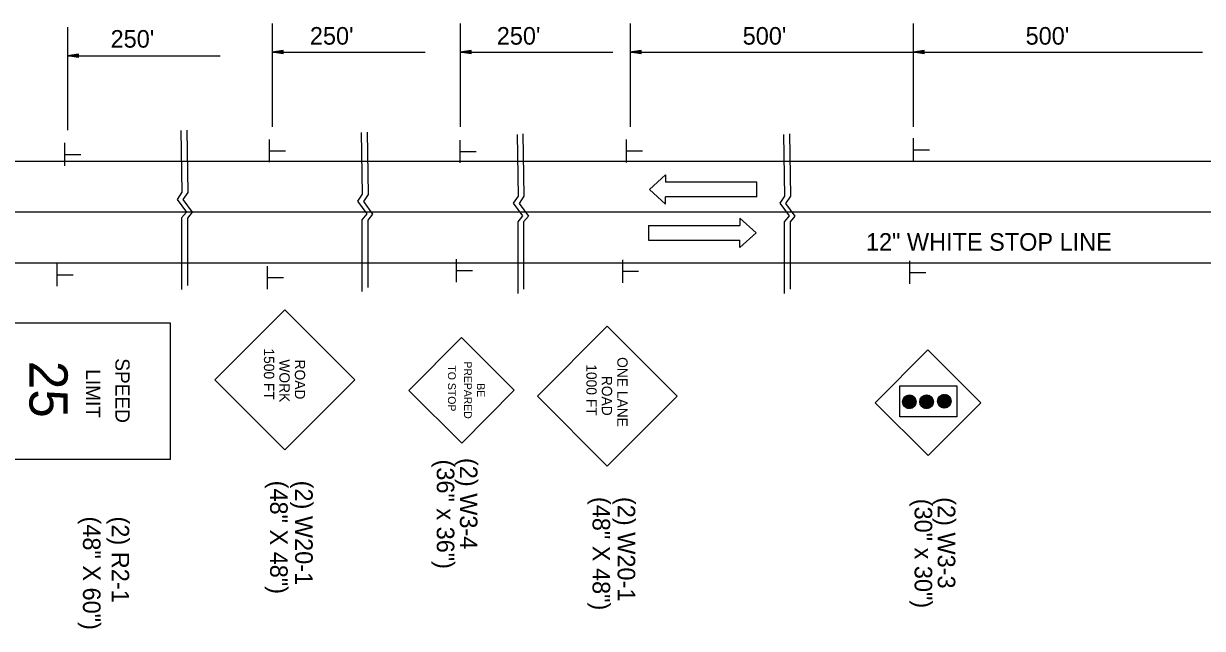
# Model space of a CAD drawing. Extents: x 1678017 to 1687792, y 404433 to 413488.
# Drawn here: x 1683876.8 to 1684279.6, y 411188.4 to 411394.9 of the extents above; entities that cross this region are included whole.
import ezdxf

# ---------------------------------------------------------------- set-up
doc = ezdxf.new("R2010")
doc.units = 0
doc.layers.add('Default', color=7, linetype='Continuous')
doc.layers.add('S_GRAVEL_ROAD', color=7, linetype='Continuous')

msp = doc.modelspace()

# ---------------------------------------------------------------- linework, layer by layer
at = {"layer": 'Default'}
for p, q in [((1683961.8, 411394.85), (1683961.8, 411359.64)), ((1684025.96, 411394.85), (1684025.96, 411359.64)), ((1684084.06, 411394.85), (1684084.06, 411359.64)), ((1684180.71, 411394.85), (1684180.71, 411359.64)), ((1683891.83, 411393.65), (1683891.83, 411358.44)), ((1683895.58, 411384.42), (1683891.83, 411383.86)), ((1683891.83, 411383.86), (1683944.02, 411383.86)), ((1683895.58, 411383.3), (1683891.83, 411383.86)), ((1683895.58, 411384.33), (1683892.46, 411383.86)), ((1683895.58, 411383.39), (1683892.46, 411383.86)), ((1683895.58, 411384.24), (1683893.1, 411383.86)), ((1683895.58, 411383.49), (1683893.1, 411383.86)), ((1683895.58, 411384.14), (1683893.73, 411383.86)), ((1683895.58, 411383.58), (1683893.73, 411383.86)), ((1683895.58, 411384.05), (1683894.36, 411383.86)), ((1683895.58, 411383.68), (1683894.36, 411383.86)), ((1683895.58, 411383.95), (1683894.99, 411383.86)), ((1683895.58, 411383.77), (1683894.99, 411383.86)), ((1683895.58, 411383.3), (1683895.58, 411384.42)), ((1683965.55, 411385.62), (1683961.8, 411385.06)), ((1683961.8, 411385.06), (1684013.99, 411385.06)), ((1683965.55, 411384.5), (1683961.8, 411385.06)), ((1683965.55, 411385.53), (1683962.42, 411385.06)), ((1683965.55, 411384.59), (1683962.42, 411385.06)), ((1683965.55, 411385.43), (1683963.07, 411385.06)), ((1683965.55, 411384.69), (1683963.07, 411385.06)), ((1683965.55, 411385.34), (1683963.69, 411385.06)), ((1683965.55, 411384.78), (1683963.69, 411385.06)), ((1683965.55, 411385.25), (1683964.33, 411385.06)), ((1683965.55, 411384.88), (1683964.33, 411385.06)), ((1683965.55, 411385.15), (1683964.96, 411385.06)), ((1683965.55, 411384.97), (1683964.96, 411385.06)), ((1683965.55, 411384.5), (1683965.55, 411385.62)), ((1684029.71, 411385.62), (1684025.96, 411385.06)), ((1684025.96, 411385.06), (1684078.15, 411385.06)), ((1684029.71, 411384.5), (1684025.96, 411385.06)), ((1684029.71, 411385.53), (1684026.58, 411385.06)), ((1684029.71, 411384.59), (1684026.58, 411385.06)), ((1684029.71, 411385.43), (1684027.23, 411385.06)), ((1684029.71, 411384.69), (1684027.23, 411385.06)), ((1684029.71, 411385.34), (1684027.85, 411385.06)), ((1684029.71, 411384.78), (1684027.85, 411385.06)), ((1684029.71, 411385.25), (1684028.49, 411385.06)), ((1684029.71, 411384.88), (1684028.49, 411385.06)), ((1684029.71, 411385.15), (1684029.12, 411385.06)), ((1684029.71, 411384.97), (1684029.12, 411385.06)), ((1684029.71, 411384.5), (1684029.71, 411385.62)), ((1684087.81, 411385.62), (1684084.06, 411385.06)), ((1684084.06, 411385.06), (1684181.55, 411385.06)), ((1684087.81, 411384.5), (1684084.06, 411385.06)), ((1684087.81, 411385.53), (1684084.69, 411385.06)), ((1684087.81, 411384.59), (1684084.69, 411385.06)), ((1684087.81, 411385.43), (1684085.33, 411385.06)), ((1684087.81, 411384.69), (1684085.33, 411385.06)), ((1684087.81, 411385.34), (1684085.96, 411385.06)), ((1684087.81, 411384.78), (1684085.96, 411385.06)), ((1684087.81, 411385.25), (1684086.59, 411385.06)), ((1684087.81, 411384.88), (1684086.59, 411385.06)), ((1684087.81, 411385.15), (1684087.22, 411385.06)), ((1684087.81, 411384.97), (1684087.22, 411385.06)), ((1684087.81, 411384.5), (1684087.81, 411385.62)), ((1684184.46, 411385.62), (1684180.71, 411385.06)), ((1684180.71, 411385.06), (1684279.55, 411385.06)), ((1684184.46, 411384.5), (1684180.71, 411385.06)), ((1684184.46, 411385.53), (1684181.34, 411385.06)), ((1684184.46, 411384.59), (1684181.34, 411385.06)), ((1684184.46, 411385.43), (1684181.98, 411385.06)), ((1684184.46, 411384.69), (1684181.98, 411385.06)), ((1684184.46, 411385.34), (1684182.61, 411385.06)), ((1684184.46, 411384.78), (1684182.61, 411385.06)), ((1684184.46, 411385.25), (1684183.24, 411385.06)), ((1684184.46, 411384.88), (1684183.24, 411385.06)), ((1684184.46, 411385.15), (1684183.87, 411385.06)), ((1684184.46, 411384.97), (1684183.87, 411385.06)), ((1684184.46, 411384.5), (1684184.46, 411385.62)), ((1683890.92, 411346.31), (1683890.92, 411354.13)), ((1683960.89, 411347.51), (1683960.89, 411355.33)), ((1684025.96, 411347.27), (1684025.96, 411355.09)), ((1684082.76, 411347.48), (1684082.76, 411355.31)), ((1684180.9, 411347.9), (1684180.9, 411355.73)), ((1683891.04, 411350.2), (1683896.38, 411350.2)), ((1683961, 411351.4), (1683966.34, 411351.4)), ((1684026.07, 411351.16), (1684031.41, 411351.16)), ((1684082.88, 411351.37), (1684088.22, 411351.37)), ((1684181.01, 411351.79), (1684186.36, 411351.79)), ((1683849.88, 411347.94), (1683923.82, 411347.94)), ((1683923.82, 411347.94), (1683985.79, 411347.94)), ((1683985.79, 411347.94), (1684046.64, 411347.94)), ((1684046.64, 411347.94), (1684133.24, 411347.94)), ((1684133.24, 411347.94), (1684293.16, 411347.94)), ((1683849.88, 411330.56), (1683924.27, 411330.56)), ((1683924.27, 411330.56), (1683985.45, 411330.56)), ((1683985.45, 411330.56), (1684046.64, 411330.56)), ((1684046.64, 411330.56), (1684133.24, 411330.56)), ((1684133.24, 411330.56), (1684293.16, 411330.56)), ((1684024.69, 411306.63), (1684024.69, 411314.45)), ((1684081.5, 411306.42), (1684081.5, 411314.24)), ((1684179.64, 411305.99), (1684179.64, 411313.82)), ((1683849.88, 411313.17), (1683924.73, 411313.17)), ((1683888.35, 411305.25), (1683888.35, 411313.08)), ((1683924.73, 411313.17), (1683985.11, 411313.17)), ((1683960.21, 411304.24), (1683960.21, 411312.07)), ((1683985.11, 411313.17), (1684059.46, 411313.17)), ((1684024.81, 411310.52), (1684030.15, 411310.52)), ((1684046.64, 411313.17), (1684142.41, 411313.17)), ((1684081.61, 411310.31), (1684086.95, 411310.31)), ((1684133.24, 411313.17), (1684293.16, 411313.17)), ((1684179.75, 411309.88), (1684185.09, 411309.88)), ((1683888.46, 411309.14), (1683893.8, 411309.14)), ((1683960.33, 411308.14), (1683965.67, 411308.14)), ((1683942.22, 411273.26), (1683966.11, 411297.17)), ((1683990.01, 411273.26), (1683966.11, 411297.17)), ((1684052.37, 411267.71), (1684076.25, 411291.61)), ((1684100.16, 411267.71), (1684076.25, 411291.61)), ((1684008.42, 411269.65), (1684026.43, 411287.72)), ((1684044.49, 411269.71), (1684026.43, 411287.72)), ((1684167.77, 411265.4), (1684185.78, 411283.47)), ((1684203.84, 411265.46), (1684185.78, 411283.47)), ((1683966.11, 411249.36), (1683942.22, 411273.26)), ((1683966.11, 411249.36), (1683990.01, 411273.26)), ((1684026.5, 411251.64), (1684008.42, 411269.65)), ((1684026.5, 411251.64), (1684044.49, 411269.71)), ((1684076.25, 411243.81), (1684052.37, 411267.71)), ((1684076.25, 411243.81), (1684100.16, 411267.71)), ((1684185.84, 411247.39), (1684167.77, 411265.4)), ((1684177.11, 411265.8), (1684179.48, 411263.43)), ((1684177.11, 411265.66), (1684179.34, 411263.43)), ((1684177.12, 411265.94), (1684179.62, 411263.44)), ((1684177.12, 411265.5), (1684179.18, 411263.44)), ((1684177.13, 411266.07), (1684179.75, 411263.45)), ((1684177.15, 411266.19), (1684179.87, 411263.47)), ((1684177.15, 411265.33), (1684179.01, 411263.47)), ((1684177.18, 411266.31), (1684179.99, 411263.5)), ((1684177.21, 411266.42), (1684180.1, 411263.53)), ((1684177.24, 411266.53), (1684180.21, 411263.56)), ((1684177.32, 411266.73), (1684180.41, 411263.64)), ((1684177.37, 411266.83), (1684180.51, 411263.69)), ((1684177.42, 411266.92), (1684180.6, 411263.74)), ((1684177.48, 411267.01), (1684180.69, 411263.8)), ((1684177.53, 411267.1), (1684180.78, 411263.85)), ((1684177.59, 411267.18), (1684180.86, 411263.91)), ((1684177.66, 411267.26), (1684180.94, 411263.98)), ((1684177.72, 411267.34), (1684181.02, 411264.04)), ((1684177.79, 411267.41), (1684181.09, 411264.12)), ((1684177.87, 411267.48), (1684181.16, 411264.19)), ((1684177.94, 411267.54), (1684181.22, 411264.26)), ((1684178.02, 411267.61), (1684181.29, 411264.34)), ((1684178.11, 411267.67), (1684181.35, 411264.43)), ((1684178.19, 411267.73), (1684181.41, 411264.51)), ((1684178.28, 411267.78), (1684181.46, 411264.6)), ((1684178.38, 411267.83), (1684181.51, 411264.7)), ((1684178.47, 411267.88), (1684181.56, 411264.79)), ((1684178.57, 411267.92), (1684181.6, 411264.89)), ((1684178.68, 411267.96), (1684181.64, 411265)), ((1684178.79, 411267.99), (1684181.67, 411265.11)), ((1684178.9, 411268.02), (1684181.7, 411265.22)), ((1684179.02, 411268.05), (1684181.73, 411265.34)), ((1684179.14, 411268.07), (1684181.75, 411265.46)), ((1684179.27, 411268.08), (1684181.76, 411265.59)), ((1684179.41, 411268.09), (1684181.77, 411265.73)), ((1684179.55, 411268.08), (1684181.76, 411265.87)), ((1684179.71, 411268.07), (1684181.75, 411266.03)), ((1684179.88, 411268.04), (1684181.72, 411266.2)), ((1684180.07, 411268), (1684181.68, 411266.39)), ((1684180.28, 411267.93), (1684181.61, 411266.6)), ((1684180.55, 411267.8), (1684181.48, 411266.87)), ((1684183, 411265.86), (1684185.43, 411263.43)), ((1684183, 411265.72), (1684185.29, 411263.43)), ((1684183.01, 411266), (1684185.57, 411263.44)), ((1684183.01, 411265.57), (1684185.14, 411263.44)), ((1684183.02, 411265.41), (1684184.98, 411263.46)), ((1684183.03, 411266.12), (1684185.69, 411263.46)), ((1684183.05, 411266.24), (1684185.81, 411263.48)), ((1684183.08, 411266.36), (1684185.93, 411263.51)), ((1684183.11, 411266.47), (1684186.04, 411263.54)), ((1684183.15, 411266.58), (1684186.15, 411263.58)), ((1684183.19, 411266.68), (1684186.25, 411263.62)), ((1684183.23, 411266.78), (1684186.35, 411263.66)), ((1684183.28, 411266.87), (1684186.44, 411263.71)), ((1684183.33, 411266.96), (1684186.53, 411263.77)), ((1684183.39, 411267.05), (1684186.62, 411263.82)), ((1684183.45, 411267.13), (1684186.7, 411263.88)), ((1684183.51, 411267.22), (1684186.78, 411263.94)), ((1684183.58, 411267.29), (1684186.86, 411264.01)), ((1684183.64, 411267.37), (1684186.94, 411264.08)), ((1684183.72, 411267.44), (1684187.01, 411264.15)), ((1684183.79, 411267.51), (1684187.08, 411264.22)), ((1684183.87, 411267.57), (1684187.14, 411264.3)), ((1684183.95, 411267.64), (1684187.2, 411264.38)), ((1684184.03, 411267.69), (1684187.26, 411264.47)), ((1684184.12, 411267.75), (1684187.32, 411264.55)), ((1684184.21, 411267.8), (1684187.37, 411264.64)), ((1684184.31, 411267.85), (1684187.42, 411264.74)), ((1684184.4, 411267.9), (1684187.46, 411264.84)), ((1684184.51, 411267.94), (1684187.51, 411264.94)), ((1684184.61, 411267.97), (1684187.54, 411265.04)), ((1684184.72, 411268.01), (1684187.58, 411265.15)), ((1684184.84, 411268.03), (1684187.6, 411265.27)), ((1684184.96, 411268.06), (1684187.63, 411265.39)), ((1684185.09, 411268.07), (1684187.64, 411265.52)), ((1684185.22, 411268.08), (1684187.65, 411265.65)), ((1684185.36, 411268.09), (1684187.65, 411265.79)), ((1684185.51, 411268.08), (1684187.65, 411265.94)), ((1684185.67, 411268.06), (1684187.63, 411266.1)), ((1684185.84, 411247.39), (1684203.84, 411265.46)), ((1684185.85, 411268.03), (1684187.6, 411266.28)), ((1684186.05, 411267.97), (1684187.54, 411266.48)), ((1684186.28, 411267.88), (1684187.45, 411266.71)), ((1684186.59, 411267.71), (1684187.28, 411267.03)), ((1684189.06, 411266.08), (1684191.5, 411263.65)), ((1684189.06, 411265.94), (1684191.35, 411263.64)), ((1684189.07, 411266.21), (1684191.63, 411263.65)), ((1684189.07, 411265.79), (1684191.2, 411263.65)), ((1684189.09, 411266.34), (1684191.76, 411263.67)), ((1684189.09, 411265.62), (1684191.04, 411263.67)), ((1684189.11, 411266.46), (1684191.88, 411263.69)), ((1684189.12, 411265.45), (1684190.87, 411263.7)), ((1684189.14, 411266.57), (1684191.99, 411263.72)), ((1684189.17, 411266.68), (1684192.1, 411263.75)), ((1684189.21, 411266.79), (1684192.21, 411263.79)), ((1684189.25, 411266.89), (1684192.31, 411263.83)), ((1684189.3, 411266.99), (1684192.41, 411263.88)), ((1684189.34, 411267.08), (1684192.5, 411263.93)), ((1684189.4, 411267.18), (1684192.59, 411263.98)), ((1684189.45, 411267.26), (1684192.68, 411264.03)), ((1684189.51, 411267.35), (1684192.77, 411264.09)), ((1684189.57, 411267.43), (1684192.85, 411264.16)), ((1684189.64, 411267.51), (1684192.92, 411264.22)), ((1684189.71, 411267.58), (1684193, 411264.29)), ((1684189.78, 411267.65), (1684193.07, 411264.36)), ((1684189.85, 411267.72), (1684193.14, 411264.44)), ((1684189.93, 411267.79), (1684193.2, 411264.51)), ((1684190.01, 411267.85), (1684193.27, 411264.59)), ((1684190.1, 411267.91), (1684193.33, 411264.68)), ((1684190.18, 411267.96), (1684193.38, 411264.77)), ((1684190.27, 411268.02), (1684193.43, 411264.86)), ((1684190.37, 411268.06), (1684193.48, 411264.95)), ((1684190.47, 411268.11), (1684193.53, 411265.05)), ((1684190.57, 411268.15), (1684193.57, 411265.15)), ((1684190.68, 411268.19), (1684193.61, 411265.26)), ((1684190.79, 411268.22), (1684193.64, 411265.37)), ((1684190.9, 411268.25), (1684193.67, 411265.48)), ((1684191.02, 411268.27), (1684193.69, 411265.6)), ((1684191.15, 411268.29), (1684193.71, 411265.73)), ((1684191.28, 411268.3), (1684193.72, 411265.86)), ((1684191.42, 411268.3), (1684193.72, 411266)), ((1684191.57, 411268.29), (1684193.71, 411266.16)), ((1684191.73, 411268.27), (1684193.69, 411266.32)), ((1684191.91, 411268.24), (1684193.66, 411266.49)), ((1684192.11, 411268.19), (1684193.6, 411266.69)), ((1684192.34, 411268.1), (1684193.51, 411266.92)), ((1684192.66, 411267.92), (1684193.34, 411267.24)), ((1684177.19, 411265.15), (1684178.83, 411263.51)), ((1684177.26, 411264.94), (1684178.62, 411263.58)), ((1684177.37, 411264.68), (1684178.36, 411263.69)), ((1684177.68, 411264.23), (1684177.9, 411264)), ((1684183.06, 411265.23), (1684184.8, 411263.49)), ((1684183.11, 411265.04), (1684184.6, 411263.54)), ((1684183.2, 411264.8), (1684184.37, 411263.63)), ((1684183.38, 411264.49), (1684184.05, 411263.81)), ((1684189.18, 411265.25), (1684190.67, 411263.76)), ((1684189.27, 411265.02), (1684190.43, 411263.85)), ((1684189.44, 411264.7), (1684190.12, 411264.02))]:
    msp.add_line(p, q, dxfattribs=at)
for points in [[(1683930.61, 411358.31), (1683930.93, 411337.27), (1683929.3, 411334.86), (1683932.47, 411330.53), (1683930.8, 411328.53), (1683930.8, 411304.07)], [(1683932.6, 411358.5), (1683932.92, 411337.19), (1683931.3, 411334.77), (1683934.46, 411330.44), (1683932.8, 411328.44), (1683932.79, 411305.48)], [(1683992.21, 411357.65), (1683992.53, 411336.62), (1683990.91, 411334.2), (1683994.07, 411329.87), (1683992.41, 411327.87), (1683992.4, 411303.42)], [(1683994.21, 411357.84), (1683994.53, 411336.53), (1683992.91, 411334.12), (1683996.07, 411329.79), (1683994.41, 411327.79), (1683994.4, 411304.82)], [(1684045.44, 411357.02), (1684045.76, 411335.98), (1684044.13, 411333.57), (1684047.3, 411329.24), (1684045.63, 411327.24), (1684045.63, 411302.78)], [(1684047.43, 411357.21), (1684047.76, 411335.9), (1684046.13, 411333.49), (1684049.3, 411329.16), (1684047.63, 411327.16), (1684047.63, 411304.19)], [(1684136.48, 411357.02), (1684136.8, 411335.98), (1684135.18, 411333.57), (1684138.34, 411329.24), (1684136.68, 411327.24), (1684136.67, 411302.78)], [(1684138.48, 411357.21), (1684138.8, 411335.9), (1684137.18, 411333.49), (1684140.34, 411329.16), (1684138.68, 411327.16), (1684138.67, 411304.19)]]:
    msp.add_lwpolyline(points, dxfattribs=at)
for points in [[(1683926.87, 411246.06), (1683868, 411246.06), (1683868, 411292.76), (1683926.87, 411292.76)], [(1684195.63, 411271.18), (1684195.63, 411260.65), (1684176.2, 411260.65), (1684176.2, 411271.18)]]:
    msp.add_lwpolyline(points, close=True, dxfattribs=at)
for centre in [(1684179.44, 411265.76), (1684185.33, 411265.76), (1684191.39, 411265.97)]:
    msp.add_circle(centre, 2.33, dxfattribs=at)
at = {"layer": 'S_GRAVEL_ROAD'}
for p, q in [((1684090.61, 411338.26), (1684096.1, 411343.26)), ((1684096.1, 411343.26), (1684096.1, 411340.76)), ((1684096.1, 411333.26), (1684090.61, 411338.26)), ((1684127.32, 411340.76), (1684096.1, 411340.76)), ((1684127.32, 411335.76), (1684127.32, 411340.76)), ((1684127.32, 411335.76), (1684096.1, 411335.76)), ((1684096.1, 411333.26), (1684096.1, 411335.76)), ((1684090.36, 411325.93), (1684121.58, 411325.93)), ((1684090.36, 411325.93), (1684090.36, 411320.93)), ((1684121.58, 411328.43), (1684127.06, 411323.43)), ((1684121.58, 411328.43), (1684121.58, 411325.93)), ((1684127.06, 411323.43), (1684121.58, 411318.43)), ((1684090.36, 411320.93), (1684121.58, 411320.93)), ((1684121.58, 411318.43), (1684121.58, 411320.93))]:
    msp.add_line(p, q, dxfattribs=at)

# ---------------------------------------------------------------- texts
at = {"layer": 'Default'}
for s, p in [("250'", (1683906.57, 411386.64)), ("250'", (1683974.65, 411387.67)), ("250'", (1684038.49, 411387.67)), ("500'", (1684122.5, 411387.67)), ("500'", (1684219.15, 411387.67)), ('12" WHITE STOP LINE', (1684164.6, 411317.33))]:
    msp.add_text(s, height=6, dxfattribs=at).set_placement(p)
for s, height, rotation, p in [('1500 FT', 3.522, 270.0006, (1683958.95, 411283.98)), ('25', 13.039, 270, (1683878.85, 411279.71)), ('SPEED', 4.865, 270, (1683908.2, 411280.61)), ('WORK', 3.52, 270, (1683964.23, 411280.24)), ('ROAD', 3.521, 270.0004, (1683969.51, 411280.17)), ('TO STOP', 2.675, 270.0006, (1684021.81, 411278.18)), ('PREPARED', 2.658, 270.1003, (1684027.28, 411279.53)), ('1000 FT', 3.522, 270.0006, (1684069.1, 411278.57)), ('ONE LANE', 3.521, 270.0004, (1684079.66, 411281.01)), ('LIMIT', 4.865, 270, (1683898.15, 411276.88)), ('ROAD', 3.52, 270, (1684074.38, 411274.62)), ('BE', 2.658, 270.1004, (1684031.73, 411272.07)), ('(36" x 36")', 6, 270, (1684017.99, 411246.06)), ('(2) W3-4', 6, 270, (1684025.89, 411246.6)), ('(48" X 48")', 6, 270, (1683961.06, 411238.85)), ('(2) W20-1', 6, 270, (1683969.62, 411238.85)), ('(48" X 48")', 6, 270, (1684071.21, 411233.29)), ('(2) W20-1', 6, 270, (1684079.77, 411233.29)), ('(30" x 30")', 6, 270, (1684181.23, 411232.68)), ('(2) W3-3', 6, 270, (1684189.13, 411233.21)), ('(48" X 60")', 6, 270, (1683897.13, 411226.61)), ('(2) R2-1', 6, 270, (1683906.91, 411226.61))]:
    msp.add_text(s, height=height, rotation=rotation, dxfattribs=at).set_placement(p)

doc.saveas('drawing.dxf')
